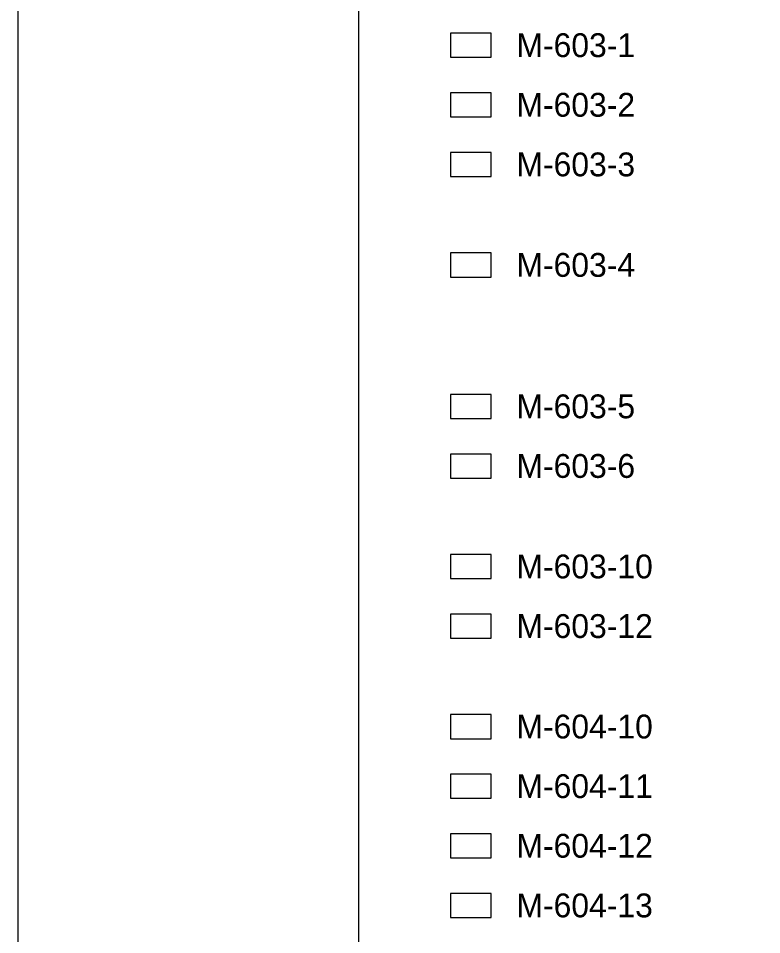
# Model space of a CAD drawing. Extents: x 0 to 1.42, y 0 to 0.92.
# Drawn here: x 0 to 0.1819, y 0.2353 to 0.4595 of the extents above; entities that cross this region are included whole.
import ezdxf

# ---------------------------------------------------------------- set-up
doc = ezdxf.new("R2010")
doc.units = 0
for name, color, linetype in [('DRAFT_Text-Notes', 7, 'Continuous'), ('SHEET_Lines', 7, 'Continuous'), ('SHEET_Plot Boundary', 7, 'Continuous')]:
    doc.layers.add(name, color=color, linetype=linetype)

msp = doc.modelspace()

# ---------------------------------------------------------------- linework, layer by layer
at = {"layer": 'SHEET_Lines'}
msp.add_lwpolyline([(0.08333, 0.875), (1.375, 0.875), (1.375, 0.125), (0.08333, 0.125)], close=True, dxfattribs=at)
for points in [[(0.10578, 0.45), (0.11575, 0.45), (0.11575, 0.45588), (0.10578, 0.45588), (0.10578, 0.45)], [(0.10578, 0.43541), (0.11575, 0.43541), (0.11575, 0.44129), (0.10578, 0.44129), (0.10578, 0.43541)], [(0.10578, 0.42081), (0.11575, 0.42081), (0.11575, 0.4267), (0.10578, 0.4267), (0.10578, 0.42081)], [(0.10578, 0.39622), (0.11575, 0.39622), (0.11575, 0.40211), (0.10578, 0.40211), (0.10578, 0.39622)], [(0.10578, 0.36159), (0.11575, 0.36159), (0.11575, 0.36748), (0.10578, 0.36748), (0.10578, 0.36159)], [(0.10578, 0.347), (0.11575, 0.347), (0.11575, 0.35289), (0.10578, 0.35289), (0.10578, 0.347)], [(0.10578, 0.32241), (0.11575, 0.32241), (0.11575, 0.3283), (0.10578, 0.3283), (0.10578, 0.32241)], [(0.10578, 0.30782), (0.11575, 0.30782), (0.11575, 0.3137), (0.10578, 0.3137), (0.10578, 0.30782)], [(0.10578, 0.28323), (0.11575, 0.28323), (0.11575, 0.28911), (0.10578, 0.28911), (0.10578, 0.28323)], [(0.10578, 0.26863), (0.11575, 0.26863), (0.11575, 0.27452), (0.10578, 0.27452), (0.10578, 0.26863)], [(0.10578, 0.25404), (0.11575, 0.25404), (0.11575, 0.25993), (0.10578, 0.25993), (0.10578, 0.25404)], [(0.10578, 0.23945), (0.11575, 0.23945), (0.11575, 0.24534), (0.10578, 0.24534), (0.10578, 0.23945)]]:
    msp.add_lwpolyline(points, dxfattribs=at)
at = {"layer": 'SHEET_Plot Boundary'}
msp.add_lwpolyline([(0, 0.91667), (1.41667, 0.91667), (1.41667, 0), (0, 0)], close=True, dxfattribs=at)

# ---------------------------------------------------------------- texts
at = {"layer": 'DRAFT_Text-Notes'}
for s, p in [('M-603-1', (0.1219, 0.45005)), ('M-603-2', (0.1219, 0.43546)), ('M-603-3', (0.1219, 0.42087)), ('M-603-4', (0.1219, 0.39627)), ('M-603-5', (0.1219, 0.36165)), ('M-603-6', (0.1219, 0.34706)), ('M-603-10', (0.1219, 0.32246)), ('M-603-12', (0.1219, 0.30787)), ('M-604-10', (0.1219, 0.28328)), ('M-604-11', (0.1219, 0.26869)), ('M-604-12', (0.1219, 0.2541)), ('M-604-13', (0.1219, 0.2395))]:
    msp.add_text(s, height=0.005833, dxfattribs=at).set_placement(p)

doc.saveas('drawing.dxf')
